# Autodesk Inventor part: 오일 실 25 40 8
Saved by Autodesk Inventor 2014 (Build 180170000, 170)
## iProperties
Created: 2026-04
Part Number: 오일 실 25 40 8
Material: 고무
Document SubType Name: Modeling
Designer: dg
Density: 0.93 g/cm^3
Appearance: 고무 - 검은색 - 버전 1.1
Author: jhkim
Description: 오일-실
Creation Date: 2026-03-27
Sending System: Autodesk Inventor 2026
Preprocessor: ST-DEVELOPER v20.1
Author: dg
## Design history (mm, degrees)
node "오일 실 25 40 81"
body "Solid1"
node "기준1"
